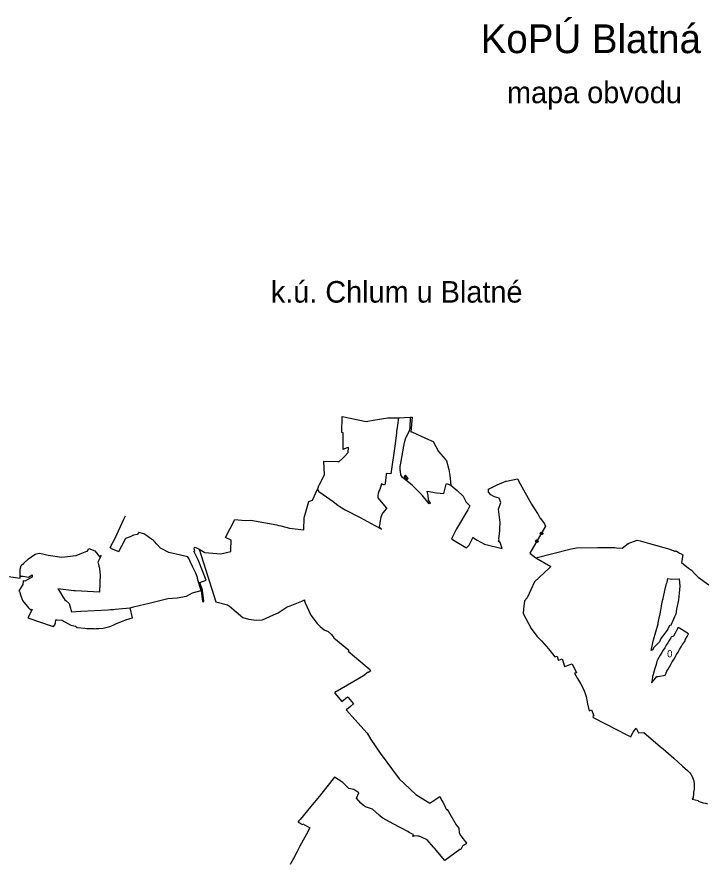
# Model space of a CAD drawing. Extents: x -795532 to -788149, y -1112756 to -1107628.
# Drawn here: x -793659 to -791742, y -1109980 to -1107628 of the extents above; entities that cross this region are included whole.
import ezdxf

# ---------------------------------------------------------------- set-up
doc = ezdxf.new("R2010")
doc.units = 0
for name, color, linetype in [('HRA_KU', 7, 'Continuous'), ('KU_OST', 7, 'Continuous'), ('NERES_SET', 7, 'Continuous'), ('OVNE_PRE', 7, 'Continuous'), ('OVNE_SET', 7, 'Continuous'), ('OVNI_SET', 7, 'Continuous'), ('POPIS', 7, 'Continuous'), ('POZN', 7, 'Continuous')]:
    doc.layers.add(name, color=color, linetype=linetype)

msp = doc.modelspace()

# ---------------------------------------------------------------- linework, layer by layer
at = {"layer": 'HRA_KU'}
for points in [[(-792597.3, -1108743.4), (-792563.7, -1108741.7)], [(-792451.5, -1108930.9), (-792434.4, -1108946.4), (-792417.6, -1108961.7), (-792409.5, -1108978.8), (-792398.7, -1108988.7), (-792404.9, -1108999.4), (-792436.1, -1109052.7), (-792447.8, -1109077.1), (-792449.7, -1109081.1), (-792447.1, -1109082.7), (-792410.3, -1109104.4), (-792408.6, -1109105.4), (-792405.3, -1109102.5), (-792400.8, -1109098.4), (-792397, -1109090.8), (-792391.3, -1109079.4), (-792389.9, -1109076.6), (-792385.8, -1109079.1), (-792378.2, -1109083.8), (-792368.7, -1109089.6), (-792358.6, -1109095.7), (-792308.8, -1109107.3), (-792314.7, -1109090.4), (-792318.8, -1109088.1), (-792317.2, -1109083.6), (-792318.4, -1109080.5), (-792315.6, -1109058.7), (-792315.2, -1109052.2), (-792314.2, -1109035), (-792317.5, -1109012.6), (-792318.8, -1108997.5), (-792312.3, -1108979.8), (-792317.4, -1108966.9), (-792330.3, -1108963.7), (-792340.1, -1108957.7), (-792346.6, -1108950.5), (-792346.8, -1108942.2), (-792323.1, -1108930.2), (-792298.8, -1108920.3), (-792297, -1108919.6), (-792266.4, -1108913.2), (-792258.6, -1108927.6), (-792227.1, -1108983.9), (-792221, -1108994.6), (-792209.3, -1109013.1), (-792206.6, -1109016.5), (-792204.2, -1109021.9), (-792203.5, -1109023), (-792193.5, -1109035.7), (-792191.4, -1109038.7), (-792188.1, -1109045.6), (-792232.4, -1109120.7), (-792215.6, -1109133.1)], [(-793151.8, -1109109.5), (-793135.8, -1109118.4), (-793091.3, -1109122.6), (-793063.7, -1109116.1), (-793063.5, -1109112.2), (-793063.4, -1109107.2), (-793063.1, -1109088.1), (-793063.1, -1109084.2), (-793078.8, -1109077.2), (-793053, -1109027.1), (-793024.2, -1109029.1), (-793008.4, -1109029), (-792935.6, -1109041.7), (-792930.7, -1109043), (-792924.6, -1109044.5), (-792900.9, -1109050.4), (-792860.3, -1109055.1), (-792860.2, -1109022), (-792847.1, -1108976.9), (-792836.4, -1108973.2), (-792822.6, -1108942.1)], [(-793146, -1109224.1), (-793148.8, -1109215.5), (-793155.7, -1109194.4), (-793156.2, -1109188.3), (-793160.9, -1109175.8), (-793170, -1109157.5), (-793176.7, -1109143.8), (-793181, -1109135.2), (-793183.8, -1109130.5), (-793236.4, -1109118.3), (-793257.6, -1109107.7), (-793259, -1109106.6), (-793269.7, -1109095), (-793276.4, -1109087.9), (-793279, -1109084.9), (-793290, -1109077.4), (-793294.4, -1109074.4), (-793305.5, -1109066.9), (-793319.7, -1109062.4), (-793324, -1109068.8), (-793334.4, -1109070.6), (-793343.4, -1109075.1), (-793357.1, -1109079.9), (-793368.1, -1109101.1), (-793375.9, -1109116.3), (-793377.4, -1109115.7), (-793397.1, -1109107.5), (-793396.6, -1109106.1), (-793399.5, -1109104.9), (-793385.7, -1109078.4), (-793361, -1109025.6), (-793356.7, -1109016.6)], [(-792197.7, -1109068.1), (-792200.3, -1109068.8), (-792202.6, -1109067.4), (-792203.3, -1109064.8), (-792201.9, -1109062.5), (-792199.3, -1109061.8), (-792197, -1109063.2), (-792196.3, -1109065.8), (-792197.7, -1109068.1), (-792198, -1109067.8), (-792196.7, -1109065.8), (-792197, -1109064.7), (-792199.1, -1109068.1), (-792200.1, -1109068.4), (-792197.3, -1109063.6), (-792198, -1109063.2), (-792200.8, -1109068), (-792201.5, -1109067.6), (-792198.7, -1109062.7), (-792199.4, -1109062.3), (-792202.2, -1109067.2), (-792202.5, -1109066.1), (-792200.5, -1109062.6), (-792201.6, -1109062.9), (-792202.8, -1109065)], [(-792210.4, -1109089.6), (-792213, -1109090.3), (-792215.3, -1109088.9), (-792216, -1109086.3), (-792214.6, -1109084), (-792212, -1109083.3), (-792209.7, -1109084.7), (-792209, -1109087.3), (-792210.4, -1109089.6), (-792210.6, -1109089.2), (-792209.3, -1109087.1), (-792209.6, -1109086), (-792211.6, -1109089.5), (-792212.7, -1109089.7), (-792209.9, -1109084.9), (-792210.6, -1109084.5), (-792213.4, -1109089.3), (-792214.1, -1109088.9), (-792211.3, -1109084.1), (-792212, -1109083.7), (-792214.8, -1109088.5), (-792215.1, -1109087.4), (-792213.1, -1109084), (-792214.2, -1109084.3), (-792215.4, -1109086.3)], [(-793650, -1109182.9), (-793649.6, -1109164.8), (-793646.7, -1109155), (-793639.6, -1109148.1), (-793626.5, -1109136), (-793608.4, -1109123.1), (-793597, -1109120.7), (-793586.6, -1109122.1), (-793571.8, -1109126.3), (-793534, -1109131.3), (-793493.5, -1109126.7), (-793483.2, -1109122.6), (-793464.5, -1109115.1), (-793463.4, -1109115.6), (-793458.4, -1109107.7), (-793441.7, -1109113.8), (-793428.3, -1109131.6), (-793424.5, -1109126.9), (-793433.4, -1109145.3), (-793430.9, -1109154.8), (-793430.5, -1109156.4), (-793429.6, -1109159.4), (-793429.3, -1109160.7), (-793427.8, -1109175), (-793427.5, -1109178.5), (-793429.1, -1109228.7), (-793495.7, -1109225), (-793500.1, -1109224.8), (-793500.4, -1109224.8), (-793544.8, -1109219.3), (-793542.5, -1109223), (-793540.5, -1109226.1), (-793530.9, -1109241.6), (-793525.5, -1109250), (-793521.5, -1109253.2), (-793513, -1109260.1), (-793511.1, -1109266.9), (-793506.5, -1109283.2), (-793480.7, -1109281.8), (-793404.5, -1109277.7), (-793398.5, -1109277.4), (-793390.2, -1109277), (-793385.6, -1109276.6), (-793375.3, -1109275.7), (-793344, -1109272.4)]]:
    msp.add_lwpolyline(points, dxfattribs=at)
at = {"layer": 'NERES_SET'}
msp.add_lwpolyline([(-792578, -1108903.6), (-792582, -1108907.1), (-792574.5, -1108915.9), (-792570.5, -1108912.4)], close=True, dxfattribs=at)
at = {"layer": 'OVNE_PRE'}
msp.add_lwpolyline([(-792215.6, -1109133.1), (-792120.4, -1109109.5), (-792116.2, -1109108.5), (-792102.6, -1109105.1), (-792043.2, -1109104.9), (-791995.5, -1109104.8), (-791991.3, -1109105.2), (-791975.7, -1109106.6), (-791958.2, -1109093.1), (-791933.3, -1109084.2), (-791925.1, -1109086.4), (-791899.6, -1109093.4), (-791842.3, -1109109.1), (-791838.9, -1109110.9), (-791838.3, -1109111.2), (-791831.4, -1109113.9), (-791830.5, -1109114.2), (-791830, -1109114.4), (-791827.3, -1109114.7), (-791825.5, -1109114.2), (-791815.6, -1109120.2), (-791813.2, -1109121.7), (-791806.5, -1109125.2), (-791810.1, -1109146.4), (-791790.4, -1109161.8), (-791782.4, -1109168.1), (-791773.1, -1109177.5), (-791763.7, -1109187), (-791734.5, -1109208.6)], dxfattribs=at)
at = {"layer": 'OVNE_SET'}
for points in [[(-792822.6, -1108942.1), (-792821.1, -1108938.5), (-792818.6, -1108932.4), (-792818, -1108931.1), (-792817.4, -1108929.6), (-792803.5, -1108902.2), (-792805.2, -1108864), (-792766.4, -1108865.1), (-792762.7, -1108865.2), (-792753, -1108856.7), (-792748.2, -1108852.5), (-792737.3, -1108840.4), (-792736.4, -1108826.6), (-792740.7, -1108827.7), (-792751.3, -1108831.7), (-792750.9, -1108785.1), (-792754.9, -1108784.2), (-792754, -1108740.4), (-792686.9, -1108753.6), (-792667.8, -1108750.5), (-792626.7, -1108743.9), (-792597.3, -1108743.4)], [(-792508.4, -1108981.4), (-792512.1, -1108982.9), (-792531.9, -1108958.8), (-792559.7, -1108931.1), (-792586.6, -1108910.2), (-792590.9, -1108902.7), (-792592.2, -1108892.4), (-792592.6, -1108889.2), (-792592.5, -1108886), (-792592.6, -1108882.9), (-792592.3, -1108879.6), (-792591.1, -1108870), (-792583, -1108822.3), (-792580.7, -1108812.1), (-792577.5, -1108801.9), (-792566.4, -1108778.9), (-792564.8, -1108772.8), (-792563.7, -1108741.7)], [(-792563.7, -1108741.7), (-792559.4, -1108741.8), (-792562.8, -1108782.5), (-792560.3, -1108783.2), (-792521.9, -1108800.6), (-792501.1, -1108809.9), (-792486.2, -1108837.4), (-792473.3, -1108852.1), (-792464.1, -1108863.7), (-792457.8, -1108887.6), (-792454.2, -1108904.3), (-792451.5, -1108930.9)], [(-792597.3, -1108743.4), (-792600.3, -1108764.1), (-792602.6, -1108781.7), (-792603.1, -1108785.3), (-792606.4, -1108816.3), (-792618.5, -1108899.9), (-792631.3, -1108898.6), (-792631.7, -1108902.2), (-792634.6, -1108925.8), (-792634.8, -1108927.6), (-792635.9, -1108931.1), (-792643.1, -1108928.6), (-792644.4, -1108927.9)], [(-792644.4, -1108927.9), (-792649.3, -1108942.9), (-792651.7, -1108947.7), (-792653.5, -1108954.3), (-792654.5, -1108959.9), (-792654.7, -1108963.4), (-792654.6, -1108966.2), (-792630.7, -1108995.5), (-792629.9, -1108994.3), (-792635.1, -1109001.9), (-792641, -1109008.1), (-792642.2, -1109009.3), (-792646.6, -1109020.5)], [(-792508.4, -1108981.4), (-792513.8, -1108972.5), (-792515.3, -1108959), (-792517.5, -1108948), (-792491.4, -1108952.8), (-792471.1, -1108954), (-792464.8, -1108928.4), (-792464, -1108926.6), (-792451.5, -1108930.9)], [(-792646.6, -1109020.5), (-792649, -1109034.9), (-792649.6, -1109038.6), (-792650.9, -1109046.2), (-792651.1, -1109047.3), (-792648.3, -1109050.2), (-792644.8, -1109053.3)], [(-793695.3, -1109183.4), (-793649.8, -1109190.2), (-793650, -1109182.9), (-793647.3, -1109184), (-793641.6, -1109184.6), (-793626.8, -1109187.5), (-793616.4, -1109180.9), (-793616.3, -1109187.3), (-793636.3, -1109197.8), (-793641.8, -1109197.6), (-793642.5, -1109207.2), (-793651.5, -1109222.2), (-793653.5, -1109225.3), (-793651.4, -1109227.1), (-793651, -1109228.9), (-793650.1, -1109233.3), (-793643.2, -1109251.9), (-793629.8, -1109267.9), (-793626.2, -1109272.2), (-793620.3, -1109279.3), (-793618.6, -1109276.5), (-793616.6, -1109277.1), (-793628.7, -1109300.1), (-793561, -1109323.2), (-793559.1, -1109323.8), (-793556.9, -1109324.5), (-793553.2, -1109319.9), (-793551.6, -1109314.2), (-793550.1, -1109306.1), (-793546.8, -1109306.3), (-793534.1, -1109306.7), (-793509, -1109321.1), (-793496.1, -1109323.8), (-793491, -1109326.8), (-793470.2, -1109329), (-793464.6, -1109329.6), (-793445.9, -1109330.4), (-793443.1, -1109330.5), (-793439.2, -1109330.4), (-793430.6, -1109329.7), (-793419.2, -1109328.6), (-793400.3, -1109324.1), (-793395.9, -1109323), (-793391.1, -1109321), (-793383.5, -1109317.3), (-793367.4, -1109310.5), (-793358.6, -1109306.9), (-793343.3, -1109302), (-793337.1, -1109300.4), (-793344, -1109272.4), (-793334.5, -1109270.1), (-793286.9, -1109258.5), (-793239.2, -1109246.8), (-793213, -1109244.7), (-793187, -1109239.6), (-793170.8, -1109231.1), (-793146, -1109224.1), (-793142.2, -1109254.9), (-793139.1, -1109254.9), (-793138.7, -1109254.1), (-793142.4, -1109223.3), (-793149.6, -1109201.8), (-793132, -1109195.4), (-793153, -1109143.1), (-793156.6, -1109135.4), (-793166.6, -1109114.8), (-793163.9, -1109112.9), (-793166, -1109108.4), (-793164.7, -1109104.4), (-793163.1, -1109103.2), (-793151.8, -1109109.5)]]:
    msp.add_lwpolyline(points, dxfattribs=at)
at = {"layer": 'OVNI_SET'}
for points in [[(-792822.6, -1108942.1), (-792819.1, -1108948.5), (-792806.9, -1108956.7), (-792779.2, -1108976.2), (-792765.9, -1108986.4), (-792754.8, -1108994.2), (-792745.4, -1108999.5), (-792704.1, -1109021.5), (-792663.6, -1109043.4), (-792657.7, -1109046.5), (-792644.8, -1109053.3)], [(-793151.8, -1109109.5), (-793105.7, -1109255.9), (-793073.4, -1109264.1), (-793067.3, -1109267.9), (-793030.6, -1109299), (-793014.8, -1109304.3), (-792993.3, -1109307.1), (-792975.9, -1109305.6), (-792944.7, -1109291.7), (-792932.1, -1109286), (-792906.7, -1109269.6), (-792898.7, -1109266.5), (-792866.7, -1109253.7)], [(-792215.6, -1109133.1), (-792173.5, -1109157.7), (-792178, -1109161.8), (-792219.2, -1109200.4), (-792239.9, -1109244.8), (-792247.2, -1109253), (-792249.6, -1109276.1), (-792250.8, -1109287.8), (-792243.3, -1109302), (-792228.5, -1109329.8), (-792212.7, -1109351.1), (-792200.5, -1109363.8), (-792199.9, -1109364.2), (-792179.9, -1109386.6), (-792169.3, -1109400.1), (-792162.4, -1109409), (-792156.3, -1109406.9), (-792152.9, -1109416.8), (-792151.1, -1109417.9), (-792142.2, -1109414.8), (-792138.8, -1109425.3), (-792135.4, -1109435.7), (-792132.8, -1109435.1), (-792128.8, -1109433.7), (-792125.1, -1109432.4), (-792114.4, -1109428.1), (-792102.3, -1109453.1), (-792107.5, -1109454.7), (-792104.3, -1109460.5), (-792099.6, -1109468.9), (-792091.6, -1109483.2), (-792082, -1109500.5), (-792075, -1109519.5), (-792072.1, -1109539.6), (-792067.4, -1109558.7), (-792065.5, -1109558), (-792060.2, -1109556.4), (-792053.7, -1109573), (-792057, -1109574.8), (-792055.7, -1109577.5), (-792019.4, -1109596.3), (-791962.3, -1109625.8), (-791951.6, -1109631.4), (-791946, -1109619.7), (-791944.8, -1109618.1), (-791939.4, -1109611), (-791936.4, -1109607.1), (-791930.2, -1109620.6), (-791914.8, -1109618.9), (-791868.6, -1109658.9), (-791866, -1109661.2), (-791864.8, -1109662.2), (-791861.6, -1109665), (-791831.5, -1109691.1), (-791807.1, -1109712.9), (-791793.2, -1109725), (-791788.3, -1109730.3), (-791787.2, -1109731.6), (-791783.9, -1109735.6), (-791779.8, -1109743.2), (-791779.6, -1109743.6), (-791778.4, -1109746.8), (-791777.5, -1109748.9), (-791776.1, -1109754.1), (-791775.5, -1109756.5), (-791774.8, -1109761.6), (-791774.6, -1109763.5), (-791774.6, -1109769.4), (-791775.4, -1109776.6), (-791776.4, -1109785.3), (-791776.8, -1109788.8), (-791778.1, -1109801.2), (-791780.5, -1109804.6), (-791763.9, -1109808.9), (-791763.1, -1109810.6), (-791758.4, -1109812.1), (-791755.4, -1109813), (-791749.6, -1109814.7), (-791743.8, -1109816.1), (-791738, -1109817.5)], [(-791871.1, -1109366.6), (-791887.8, -1109383.8), (-791890.4, -1109389.6), (-791894.2, -1109391.5), (-791887.8, -1109361.1), (-791875.5, -1109317.3), (-791874.9, -1109314.6), (-791872, -1109300.9), (-791869.6, -1109289.2), (-791867.4, -1109278.8), (-791865.5, -1109267.5), (-791863.6, -1109255.4), (-791861.5, -1109246.9), (-791856.2, -1109224.6), (-791851.5, -1109204.8), (-791850.5, -1109200.7), (-791848.4, -1109191), (-791838.1, -1109192.4), (-791816.5, -1109192.1), (-791814.9, -1109212.5)], [(-791814.9, -1109212.5), (-791816.9, -1109232.1), (-791818.8, -1109250.2), (-791819.7, -1109254.9), (-791823.7, -1109276), (-791826.3, -1109289.8), (-791829.8, -1109297.6), (-791835.2, -1109310.1), (-791840.7, -1109322.5), (-791843.9, -1109321.5), (-791848.3, -1109332.2), (-791850.3, -1109334.8), (-791864.1, -1109353.1), (-791867.6, -1109358.2), (-791871.1, -1109366.6)], [(-792866.7, -1109253.7), (-792864.6, -1109252.9), (-792858.4, -1109250.4), (-792858.7, -1109254.3), (-792857.4, -1109258.5), (-792841.6, -1109292.4), (-792823.2, -1109315.9), (-792814.8, -1109324.4), (-792804.2, -1109333.3), (-792793, -1109338.6), (-792783.4, -1109346.9), (-792776.9, -1109356.1), (-792735.7, -1109390.5), (-792737.8, -1109392.8), (-792684.9, -1109437.8), (-792679.4, -1109442.6), (-792676.6, -1109445.1), (-792676.9, -1109445.3), (-792674.3, -1109447.7), (-792677, -1109449.9), (-792680.4, -1109452.7), (-792682, -1109451.3), (-792695.1, -1109462.1), (-792721.4, -1109477.2), (-792774.9, -1109507.9), (-792774.3, -1109509.6), (-792755.4, -1109533.2), (-792738.9, -1109520.2), (-792737.6, -1109521.7), (-792722.6, -1109539.9), (-792731.1, -1109546.7), (-792736.6, -1109551.3), (-792742.9, -1109556.3), (-792741.6, -1109557.4), (-792718.7, -1109582.8), (-792684.6, -1109620.8), (-792673.9, -1109638.5), (-792648.8, -1109676.6), (-792595.6, -1109748.4), (-792548.9, -1109792.1), (-792510, -1109815.6), (-792488.3, -1109800.8), (-792483.3, -1109797.4), (-792474.5, -1109812.7), (-792470.8, -1109820), (-792467.4, -1109826.9), (-792464.2, -1109834.1), (-792462.2, -1109832.7), (-792461.6, -1109833.8), (-792458.3, -1109839.4), (-792437, -1109875.8), (-792429.3, -1109885.6), (-792428.4, -1109898.2), (-792424.2, -1109907.2), (-792408, -1109927.3), (-792409.5, -1109929.3), (-792417.8, -1109933.4), (-792419, -1109935.9), (-792420.8, -1109939.1), (-792424.3, -1109945.1), (-792427, -1109945.3), (-792468.1, -1109975.4), (-792497, -1109941.6), (-792499.8, -1109938.4), (-792517.8, -1109917.9), (-792519.1, -1109917.4), (-792540, -1109908.2), (-792543.5, -1109907.9), (-792551.5, -1109907.2), (-792557.7, -1109908.8), (-792555.7, -1109903.3), (-792558.2, -1109902), (-792567.3, -1109897.2), (-792571.3, -1109895.1), (-792612.6, -1109873.6), (-792641.2, -1109857.8), (-792648, -1109851.8), (-792648.6, -1109851.2), (-792650.7, -1109849.4), (-792669.3, -1109833), (-792689.6, -1109826.4), (-792695, -1109822), (-792702.2, -1109816.1), (-792714, -1109802.2), (-792708.1, -1109787.1), (-792722, -1109777.9), (-792735.2, -1109775.2), (-792752, -1109758.6), (-792775, -1109744)], [(-792775, -1109744), (-792814.5, -1109793.1), (-792817.5, -1109796.9), (-792841.8, -1109826.2), (-792870.6, -1109861), (-792874.3, -1109865.5), (-792876.1, -1109867.6), (-792876.9, -1109868.6), (-792864.3, -1109874.9), (-792863.7, -1109873.9), (-792844, -1109885), (-792853.2, -1109901.9), (-792862.3, -1109918.8), (-792871.4, -1109935.7), (-792880.6, -1109952.6), (-792889.7, -1109969.5), (-792898.9, -1109986.4)]]:
    msp.add_lwpolyline(points, dxfattribs=at)
msp.add_lwpolyline([(-791893.4, -1109481.1), (-791886.6, -1109472.7), (-791879.3, -1109463.9), (-791874.9, -1109463.2), (-791855.6, -1109460.2), (-791853.2, -1109454.4), (-791852.6, -1109453), (-791851, -1109449), (-791847.6, -1109443.2), (-791843.6, -1109436.5), (-791843.5, -1109436.4), (-791839.8, -1109430.1), (-791835.8, -1109423.1), (-791831.7, -1109416), (-791827.8, -1109409.3), (-791823.9, -1109402.5), (-791819.9, -1109395.5), (-791815.8, -1109388.5), (-791811.6, -1109381.3), (-791808.4, -1109375.7), (-791807.3, -1109374.2), (-791802.3, -1109367.2), (-791799, -1109362.8), (-791799.9, -1109361), (-791799, -1109359.4), (-791794.8, -1109352.2), (-791790.4, -1109344.5), (-791816, -1109329.4), (-791819.2, -1109327.6), (-791823.8, -1109335.4), (-791828.3, -1109343.1), (-791832.9, -1109350.9), (-791838.8, -1109353.8), (-791840.3, -1109356.2), (-791844.5, -1109363), (-791848.5, -1109369.7), (-791852.8, -1109376.6), (-791857, -1109383.6), (-791861.1, -1109390.3), (-791865.3, -1109397.1), (-791869.2, -1109403.9), (-791873.3, -1109410.8), (-791877, -1109416.8), (-791877.6, -1109417.9), (-791881.1, -1109430), (-791884.3, -1109441.6), (-791887.8, -1109453.9), (-791889.2, -1109459.2), (-791890.5, -1109463.9), (-791892, -1109472.9)], close=True, dxfattribs=at)

# ---------------------------------------------------------------- texts
at = {"layer": 'KU_OST'}
msp.add_text('k.ú. Chlum u Blatné', height=60, dxfattribs=at).set_placement((-792952.6, -1108423.2))
at = {"layer": 'POPIS'}
for s, height, p in [('KoPÚ Blatná', 80, (-792368.7, -1107729.1)), ('mapa obvodu', 60, (-792295.5, -1107868.4))]:
    msp.add_text(s, height=height, dxfattribs=at).set_placement(p)
at = {"layer": 'POZN'}
msp.add_text('0', height=20, dxfattribs=at).set_placement((-791850.3, -1109410))

doc.saveas('drawing.dxf')
